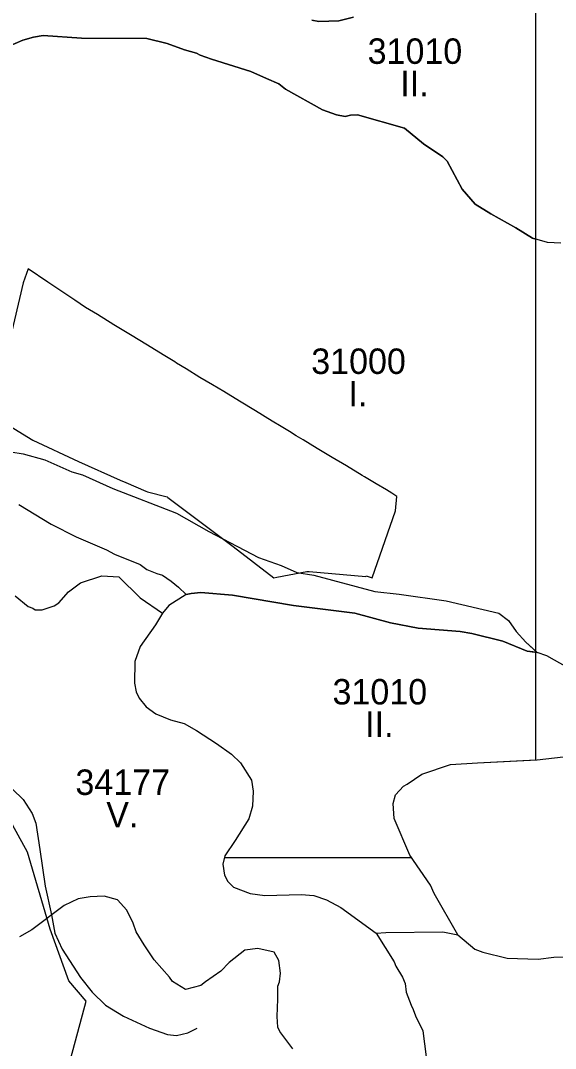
# Model space of a CAD drawing. Extents: x -555509 to -553014, y -1186753 to -1182560.
# Drawn here: x -553941 to -553520, y -1186033 to -1185224 of the extents above; entities that cross this region are included whole.
import ezdxf

# ---------------------------------------------------------------- set-up
doc = ezdxf.new("R2010")
doc.units = 0
for name, color, linetype in [('LEG_6_ZPF', 7, 'Continuous'), ('Level 29', 7, 'Continuous'), ('Level 41', 7, 'Continuous'), ('Level 52', 7, 'Continuous'), ('pěší_tr', 7, 'Continuous'), ('ZPF_I_TR_OCHRANY', 7, 'Continuous')]:
    doc.layers.add(name, color=color, linetype=linetype)

msp = doc.modelspace()

# ---------------------------------------------------------------- linework, layer by layer
at = {"layer": 'LEG_6_ZPF'}
for p, q in [((-553535.77, -1185396.28), (-553535.77, -1185130.34)), ((-553825.56, -1185242.5), (-553812, -1185247.5)), ((-553812, -1185247.5), (-553802.62, -1185250.12)), ((-553790.75, -1185254.75), (-553759.81, -1185264.5)), ((-553759.81, -1185264.5), (-553747.56, -1185270)), ((-553732.69, -1185278.5), (-553703.44, -1185294.62)), ((-553624.12, -1185321.38), (-553608.88, -1185331.5)), ((-553551.62, -1185387.5), (-553538.5, -1185395.5)), ((-553538.5, -1185395.5), (-553535.77, -1185396.28)), ((-553535.77, -1185805.56), (-553535.77, -1185721.01)), ((-553780.52, -1185882.32), (-553633.51, -1185882.32))]:
    msp.add_line(p, q, dxfattribs=at)
for points in [[(-553679.25, -1185221.75), (-553690.75, -1185224.62), (-553706.38, -1185225.12), (-553711.94, -1185224.25)], [(-553939.19, -1185239.88), (-553930.69, -1185237.38), (-553923.06, -1185236.13), (-553892.94, -1185238.25)], [(-553892.94, -1185238.25), (-553841.62, -1185238.63), (-553825.56, -1185242.5)], [(-553966.75, -1185255.63), (-553951.06, -1185245), (-553939.19, -1185239.88)], [(-553802.62, -1185250.12), (-553799.69, -1185251.75), (-553790.75, -1185254.75)], [(-553747.56, -1185270), (-553737.75, -1185274.25), (-553732.69, -1185278.5)], [(-553703.44, -1185294.62), (-553692.44, -1185298.5), (-553685.62, -1185299.75), (-553681.38, -1185298.88)], [(-553681.38, -1185298.88), (-553675.88, -1185298.5), (-553639, -1185309), (-553624.12, -1185321.38)], [(-553608.88, -1185331.5), (-553605.5, -1185334.88), (-553593.62, -1185357)], [(-553593.62, -1185357), (-553583.44, -1185368.88), (-553571.19, -1185376.5), (-553551.62, -1185387.5)], [(-553535.77, -1185721.01), (-553542.75, -1185720.25), (-553561.81, -1185712.25), (-553586, -1185706.25), (-553595.31, -1185704.63), (-553628.38, -1185702.13), (-553650, -1185697.88), (-553678, -1185690.25), (-553726.31, -1185684.25), (-553774.25, -1185676.25), (-553799.25, -1185674.12), (-553806.88, -1185674.88), (-553810.69, -1185675.75)], [(-553810.69, -1185675.75), (-553824.25, -1185684.25), (-553829.38, -1185690.25)], [(-553829.38, -1185690.25), (-553834.88, -1185699.5), (-553846.75, -1185716.5), (-553851, -1185728.38), (-553851.38, -1185745.25), (-553850.12, -1185752.12), (-553847.56, -1185757.13), (-553842.06, -1185764), (-553834.44, -1185769.5), (-553823, -1185774.13), (-553812.38, -1185777.13), (-553802.62, -1185782.63), (-553786.94, -1185792.75), (-553775.06, -1185801.25), (-553767.88, -1185808), (-553759.38, -1185821.63), (-553758.12, -1185830.13), (-553758.56, -1185842), (-553761.5, -1185852.12), (-553772.12, -1185869.12), (-553780.19, -1185881), (-553780.52, -1185882.32)], [(-553633.51, -1185882.32), (-553634.75, -1185880.5), (-553647.06, -1185851.75), (-553647.88, -1185839.88), (-553646.19, -1185833.12), (-553639.81, -1185826.25), (-553636.88, -1185824.62), (-553625.44, -1185817), (-553602.94, -1185809.38), (-553581.75, -1185808), (-553535.77, -1185805.56)]]:
    msp.add_lwpolyline(points, dxfattribs=at)
at = {"layer": 'Level 29'}
for points in [[(-553711.94, -1185224.25), (-553706.38, -1185225.12), (-553690.75, -1185224.62), (-553679.25, -1185221.75)], [(-553516.06, -1185399.38), (-553526.62, -1185398.88), (-553538.5, -1185395.5), (-553551.62, -1185387.5), (-553571.19, -1185376.5), (-553583.44, -1185368.88), (-553593.62, -1185357), (-553605.5, -1185334.88), (-553608.88, -1185331.5), (-553624.12, -1185321.38), (-553639, -1185309), (-553675.88, -1185298.5), (-553681.38, -1185298.88), (-553685.62, -1185299.75), (-553692.44, -1185298.5), (-553703.44, -1185294.62), (-553732.69, -1185278.5), (-553737.75, -1185274.25), (-553747.56, -1185270), (-553759.81, -1185264.5), (-553790.75, -1185254.75), (-553799.69, -1185251.75), (-553802.62, -1185250.12), (-553812, -1185247.5), (-553825.56, -1185242.5), (-553841.62, -1185238.63), (-553892.94, -1185238.25), (-553923.06, -1185236.13), (-553930.69, -1185237.38), (-553939.19, -1185239.88), (-553951.06, -1185245)], [(-553948.5, -1185563.38), (-553938.75, -1185565.12), (-553921.81, -1185569.75), (-553900.56, -1185579.13), (-553892.12, -1185581.62), (-553868.38, -1185592.25), (-553818.31, -1185611.75), (-553792.88, -1185626.12), (-553753.88, -1185646.5), (-553736.06, -1185652.88), (-553723.81, -1185658.38), (-553710.25, -1185660.5), (-553662.31, -1185673.25), (-553643.25, -1185675.38), (-553606.38, -1185680.5), (-553564.81, -1185690.25), (-553557.19, -1185696.13), (-553551.25, -1185704.63), (-553543.62, -1185713.13), (-553534.69, -1185721.13)], [(-553942.12, -1185605), (-553916.69, -1185620.25), (-553897.19, -1185630.38), (-553873.44, -1185640.63), (-553867.12, -1185644), (-553846.75, -1185652), (-553841.62, -1185655.88), (-553833.62, -1185659.25), (-553829.38, -1185660.5), (-553822.56, -1185665.13), (-553816.62, -1185669.88), (-553810.69, -1185675.75)], [(-553945.12, -1185676.63), (-553934.94, -1185685.13), (-553931.12, -1185686.38), (-553929.44, -1185687.62), (-553923.88, -1185687.62), (-553914.56, -1185684.63), (-553910.75, -1185682.12), (-553903.12, -1185673.63), (-553893.81, -1185666.5), (-553876.88, -1185661), (-553863.69, -1185661.75), (-553846.75, -1185678.38), (-553829.38, -1185690.25)], [(-553810.69, -1185675.75), (-553806.88, -1185674.88), (-553799.25, -1185674.12), (-553774.25, -1185676.25), (-553726.31, -1185684.25), (-553678, -1185690.25), (-553650, -1185697.88), (-553628.38, -1185702.13), (-553595.31, -1185704.63), (-553586, -1185706.25), (-553561.81, -1185712.25), (-553542.75, -1185720.25), (-553534.69, -1185721.13)], [(-553810.69, -1185675.75), (-553824.25, -1185684.25), (-553829.38, -1185690.25)], [(-553829.38, -1185690.25), (-553834.88, -1185699.5), (-553846.75, -1185716.5), (-553851, -1185728.38), (-553851.38, -1185745.25), (-553850.12, -1185752.12), (-553847.56, -1185757.13), (-553842.06, -1185764), (-553834.44, -1185769.5), (-553823, -1185774.13), (-553812.38, -1185777.13), (-553802.62, -1185782.63), (-553786.94, -1185792.75), (-553775.06, -1185801.25), (-553767.88, -1185808), (-553759.38, -1185821.63), (-553758.12, -1185830.13), (-553758.56, -1185842), (-553761.5, -1185852.12), (-553772.12, -1185869.12), (-553780.19, -1185881), (-553781.88, -1185887.75), (-553780.62, -1185896.25), (-553778.06, -1185901.38), (-553773.38, -1185905.62), (-553760.25, -1185910.63), (-553748.81, -1185912.38), (-553720.38, -1185911.5), (-553710.25, -1185912.38), (-553700.5, -1185915.75), (-553689, -1185921.62), (-553661.44, -1185942)], [(-553510.94, -1185733), (-553527.06, -1185723.75), (-553534.69, -1185721.13)], [(-553597, -1185943.25), (-553615.69, -1185910.63), (-553618.62, -1185904.25), (-553634.75, -1185880.5), (-553647.06, -1185851.75), (-553647.88, -1185839.88), (-553646.19, -1185833.12), (-553639.81, -1185826.25), (-553636.88, -1185824.62), (-553625.44, -1185817), (-553602.94, -1185809.38), (-553581.75, -1185808), (-553534.69, -1185805.5), (-553514.38, -1185803.38)], [(-553726.75, -1186032.75), (-553736.94, -1186019.25), (-553738.62, -1186015.75), (-553739.06, -1186007.38), (-553738.62, -1185993.75), (-553738.62, -1185983.63), (-553737.38, -1185980.25), (-553736.5, -1185973.38), (-553737.75, -1185963.25), (-553741.62, -1185956.88), (-553754.31, -1185953.88), (-553764.5, -1185955.12), (-553776.81, -1185964.88), (-553783.56, -1185971.75), (-553795.44, -1185980.25), (-553799.25, -1185983.12), (-553811.12, -1185986.12), (-553821.31, -1185979.75), (-553823.88, -1185976.38), (-553835.75, -1185962.75), (-553843.75, -1185951), (-553850.12, -1185940.75), (-553852.25, -1185934), (-553857.31, -1185923.75), (-553864.56, -1185915.75), (-553875.12, -1185912.75), (-553886.19, -1185913.25), (-553895.5, -1185914.88), (-553906.5, -1185920), (-553931.94, -1185939.13), (-553941.69, -1185944.63)], [(-553661.44, -1185942), (-553653.81, -1185941.25), (-553608.88, -1185940.75), (-553597, -1185943.25)], [(-553661.44, -1185942), (-553647.06, -1185964.5), (-553645.75, -1185967.88), (-553640.69, -1185976.38), (-553638.56, -1185981.5), (-553637.75, -1185988.25), (-553633.88, -1185998.38), (-553632.19, -1186001.88), (-553630.5, -1186006.88), (-553624.56, -1186018.75), (-553622.06, -1186039.12)], [(-553597, -1185943.25), (-553583.88, -1185954.38), (-553577.5, -1185956.88), (-553558.44, -1185961.5), (-553533.88, -1185962.38), (-553521.56, -1185960.75), (-553473.62, -1185960.25), (-553441.44, -1185969.13), (-553410.88, -1185988.25), (-553402.44, -1185996.75), (-553396.88, -1185999.25), (-553394.38, -1186012.38), (-553393.94, -1186022.62), (-553396.5, -1186029.38), (-553398.62, -1186039.5), (-553399, -1186042.5), (-553403.25, -1186053.13), (-553410.06, -1186063.25), (-553430.81, -1186083.62), (-553447.17, -1186102.56), (-553464.42, -1186123.36)]]:
    msp.add_lwpolyline(points, dxfattribs=at)
at = {"layer": 'Level 41'}
msp.add_lwpolyline([(-554182.98, -1186256.1), (-554155.47, -1186273.1), (-554123.11, -1186282.01), (-554072.14, -1186285.25), (-554038.97, -1186290.1), (-553977.48, -1186303.05), (-553963.73, -1186269.87), (-553952.4, -1186214.01), (-553941.07, -1186171.92), (-553908.71, -1186067.5), (-553889.29, -1185995.46), (-553903.05, -1185979.27), (-553917.61, -1185938.8), (-553935.41, -1185878.09), (-553960.49, -1185832.76), (-553991.23, -1185806.85), (-554024.41, -1185792.28), (-554055.96, -1185797.14), (-554144.15, -1185805.24), (-554079.42, -1185868.37), (-554119.88, -1185882.13), (-554123.11, -1185894.28), (-554154.67, -1186018.93), (-554200.78, -1186207.54)], dxfattribs=at)
at = {"layer": 'Level 52'}
msp.add_lwpolyline([(-553669.37, -1185661.4), (-553669.09, -1185660.85), (-553664.47, -1185662.51), (-553646.02, -1185609.88), (-553645.05, -1185598.5), (-553649.07, -1185595.88), (-553653.09, -1185593.45), (-553661.34, -1185588.67), (-553670.5, -1185583.12), (-553672.3, -1185582.14), (-553684.56, -1185574.48), (-553695.87, -1185567.84), (-553707.58, -1185560.78), (-553713.17, -1185557.43), (-553718.78, -1185553.92), (-553724.17, -1185550.89), (-553729.53, -1185547.56), (-553736.09, -1185543.66), (-553743.1, -1185539.42), (-553756.23, -1185531.27), (-553768.7, -1185523.6), (-553781.13, -1185516.16), (-553790.01, -1185510.75), (-553799.92, -1185505.11), (-553810.66, -1185498.16), (-553818.19, -1185493.66), (-553819.6, -1185492.7), (-553828.72, -1185487.23), (-553841.14, -1185479.67), (-553854.52, -1185471.56), (-553867.47, -1185463.68), (-553880.42, -1185455.64), (-553889.9, -1185450.06), (-553898.19, -1185444.23), (-553919.55, -1185429.97), (-553934.95, -1185419.61), (-553938.9, -1185430.55), (-553963.43, -1185534.75), (-553931.3, -1185554.25), (-553895.22, -1185571.18), (-553862.7, -1185585.67), (-553858.01, -1185587.49), (-553842.47, -1185594.31), (-553840.96, -1185594.97), (-553825.6, -1185598.98), (-553825.09, -1185599.26), (-553773.82, -1185637.86), (-553741.7, -1185662.44), (-553739.47, -1185662.06), (-553715.92, -1185657.49), (-553714.12, -1185657.64), (-553669.37, -1185661.4)], dxfattribs=at)
at = {"layer": 'pěší_tr'}
msp.add_lwpolyline([(-553962.71, -1185817.58), (-553954.01, -1185823.48), (-553947.23, -1185828.75), (-553938.8, -1185836.91), (-553931.88, -1185847.87), (-553928.8, -1185855.33), (-553925.65, -1185876.03), (-553921.4, -1185904.94), (-553916.61, -1185927.54), (-553914, -1185941.79), (-553908.25, -1185954.4), (-553893.72, -1185976.74), (-553884.54, -1185988.38), (-553874.13, -1185998.52), (-553859.88, -1186007.02), (-553839.46, -1186016.61), (-553825.35, -1186021.54), (-553818.22, -1186022.36), (-553809.45, -1186020.31), (-553802.06, -1186016.61)], dxfattribs=at)
at = {"layer": 'ZPF_I_TR_OCHRANY'}
msp.add_line((-553535.77, -1185720.15), (-553535.77, -1185396.28), dxfattribs=at)
for points in [[(-553535.77, -1185396.28), (-553538.5, -1185395.5), (-553551.62, -1185387.5), (-553571.19, -1185376.5), (-553583.44, -1185368.88), (-553593.62, -1185357), (-553605.5, -1185334.88), (-553608.88, -1185331.5), (-553624.12, -1185321.38), (-553639, -1185309), (-553675.88, -1185298.5), (-553681.38, -1185298.88), (-553685.62, -1185299.75), (-553692.44, -1185298.5), (-553703.44, -1185294.62), (-553732.69, -1185278.5), (-553737.75, -1185274.25), (-553747.56, -1185270), (-553759.81, -1185264.5), (-553790.75, -1185254.75), (-553799.69, -1185251.75), (-553802.62, -1185250.12), (-553812, -1185247.5), (-553825.56, -1185242.5), (-553841.62, -1185238.63), (-553892.94, -1185238.25), (-553923.06, -1185236.13), (-553930.69, -1185237.38), (-553939.19, -1185239.88), (-553951.06, -1185245)], [(-553948.5, -1185563.38), (-553938.75, -1185565.12), (-553921.81, -1185569.75), (-553900.56, -1185579.13), (-553892.12, -1185581.62), (-553868.38, -1185592.25), (-553818.31, -1185611.75), (-553792.88, -1185626.12), (-553753.88, -1185646.5), (-553736.06, -1185652.88), (-553723.81, -1185658.38), (-553710.25, -1185660.5), (-553662.31, -1185673.25), (-553643.25, -1185675.38), (-553606.38, -1185680.5), (-553564.81, -1185690.25), (-553557.19, -1185696.13), (-553551.25, -1185704.63), (-553543.62, -1185713.13), (-553535.77, -1185720.15)]]:
    msp.add_lwpolyline(points, dxfattribs=at)

# ---------------------------------------------------------------- texts
at = {"layer": 'Level 29'}
for s, p in [('31010', (-553668.03, -1185258.47)), ('II.', (-553642.36, -1185283.92)), ('31000', (-553712.36, -1185502.25)), ('I.', (-553683.06, -1185527.7)), ('31010', (-553695.65, -1185762.09)), ('II.', (-553669.98, -1185787.55)), ('34177', (-553897.75, -1185833.2)), ('V.', (-553873.5, -1185858.65))]:
    msp.add_text(s, height=20, dxfattribs=at).set_placement(p)

doc.saveas('drawing.dxf')
